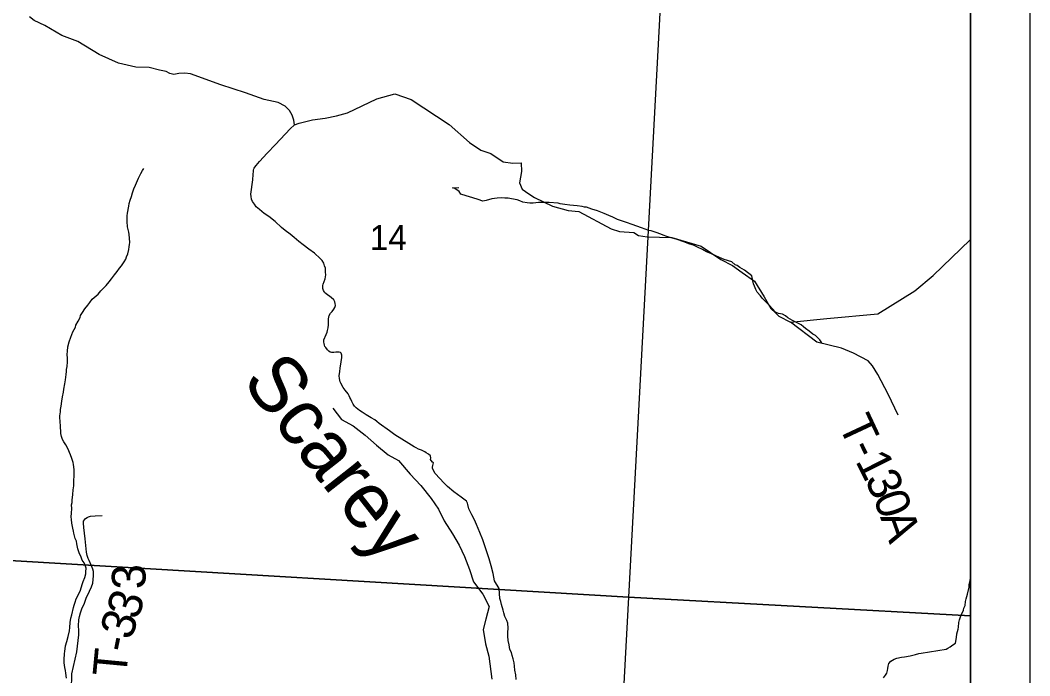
# Model space of a CAD drawing. Extents: x 0 to 45.4, y -2.2 to 22.
# Drawn here: x 7.301 to 9, y 17.906 to 19.01 of the extents above; entities that cross this region are included whole.
import ezdxf

# ---------------------------------------------------------------- set-up
doc = ezdxf.new("R2010")
doc.units = 0
for name, color, linetype in [('GM_X_Corporation', 7, 'Continuous'), ('GM_X_Minor_River', 7, 'Continuous'), ('GM_X_Minor_River_Text', 7, 'Continuous'), ('GM_X_Section_Text', 7, 'Continuous'), ('GM_X_Township_Road', 7, 'Continuous'), ('GM_X_Township_Road_Text', 7, 'Continuous'), ('SH_Data', 7, 'Continuous')]:
    doc.layers.add(name, color=color, linetype=linetype)

msp = doc.modelspace()

# ---------------------------------------------------------------- linework, layer by layer
at = {"layer": 'GM_X_Corporation'}
for points in [[(5.6021, 14.1), (7.0413, 14.1), (7.1146, 14.1136), (7.5608, 14.2194), (7.6244, 14.2444), (8.0832, 14.3972), (8.4711, 14.5406), (8.5907, 14.5823), (8.8228, 14.6772), (8.9, 14.7192), (8.9, 20.9), (2.1, 20.9)], [(5.6021, 14.1), (7.0413, 14.1), (7.1146, 14.1136), (7.5608, 14.2194), (7.6244, 14.2444), (8.0832, 14.3972), (8.4711, 14.5406), (8.5907, 14.5823), (8.8228, 14.6772), (8.9, 14.7192), (8.9, 20.9), (6.2942, 20.9), (6.2882, 20.8226), (6.2789, 20.7002), (6.2588, 20.2929), (6.2538, 20.2076), (6.2346, 20.0088), (6.2236, 19.8542), (6.181, 19.2539), (6.1763, 19.1885), (6.1061, 18.1607), (5.642, 18.1908)]]:
    msp.add_lwpolyline(points, dxfattribs=at)
for points in [[(8.3794, 19.064), (8.3245, 18.0384), (7.2262, 18.1039), (7.2905, 19.1287)], [(8.9, 18.0073), (8.9, 19.0371), (8.3794, 19.064), (8.3245, 18.0384)], [(7.2262, 18.1039), (8.3245, 18.0384), (8.2701, 17.0306), (7.1661, 17.098)], [(8.9, 16.9941), (8.9, 18.0073), (8.3245, 18.0384), (8.2701, 17.0306)]]:
    msp.add_lwpolyline(points, close=True, dxfattribs=at)
at = {"layer": 'GM_X_Minor_River'}
for points in [[(7.3803, 18.4407), (7.3801, 18.4468), (7.3805, 18.4529), (7.381, 18.4597), (7.3831, 18.4684), (7.3859, 18.4764), (7.3879, 18.4809), (7.3894, 18.4854), (7.3938, 18.4933), (7.3946, 18.4967), (7.3985, 18.5031), (7.4016, 18.5095), (7.4024, 18.5129), (7.4059, 18.5178), (7.4098, 18.5238), (7.4145, 18.5302), (7.4183, 18.5347), (7.4222, 18.5403), (7.4322, 18.5485), (7.4365, 18.5541), (7.4454, 18.5634), (7.4504, 18.5694), (7.4543, 18.5743), (7.4597, 18.581), (7.4643, 18.587), (7.4682, 18.5923), (7.4713, 18.5964), (7.4756, 18.6028), (7.4787, 18.6077), (7.4799, 18.6115), (7.4819, 18.6164), (7.4835, 18.6236), (7.484, 18.6281), (7.4848, 18.6319), (7.4853, 18.6357), (7.4846, 18.6429), (7.484, 18.649), (7.4837, 18.6528), (7.4816, 18.6619), (7.481, 18.6711), (7.4807, 18.676), (7.4808, 18.6806), (7.4812, 18.6851), (7.4837, 18.6965), (7.4842, 18.701), (7.4861, 18.7067), (7.4882, 18.7131), (7.4898, 18.7191), (7.4922, 18.7259), (7.4949, 18.7323), (7.4997, 18.7437), (7.504, 18.7516), (7.5067, 18.7568), (7.5087, 18.7602)], [(8.65, 18.4667), (8.6467, 18.4716), (8.643, 18.4751), (8.6393, 18.479), (8.6351, 18.4813), (8.6288, 18.4864), (8.6224, 18.4907), (8.6191, 18.4934), (8.615, 18.4969), (8.6007, 18.5043), (8.5928, 18.5086), (8.5887, 18.5121), (8.5838, 18.5149), (8.5804, 18.5153), (8.577, 18.5161), (8.5722, 18.5185), (8.5666, 18.5243), (8.5621, 18.5293), (8.5573, 18.5339), (8.5539, 18.5374), (8.5495, 18.542), (8.5465, 18.5459), (8.5413, 18.552), (8.5391, 18.5563), (8.5366, 18.562), (8.5351, 18.5658), (8.5337, 18.5708), (8.5319, 18.5792), (8.5196, 18.5889), (8.5121, 18.5935), (8.5076, 18.5967), (8.5042, 18.5982), (8.4983, 18.6029), (8.4858, 18.6069), (8.4727, 18.6124), (8.4629, 18.6168), (8.4561, 18.6199), (8.449, 18.6239), (8.4408, 18.6278), (8.434, 18.6309), (8.428, 18.6329), (8.4178, 18.6369), (8.405, 18.6409), (8.3926, 18.6446), (8.3892, 18.6458), (8.3828, 18.6481), (8.379, 18.6493), (8.3711, 18.6525), (8.3628, 18.6549), (8.3587, 18.6558), (8.3527, 18.6578), (8.3466, 18.6602), (8.3308, 18.6657), (8.3214, 18.6693), (8.3143, 18.6717), (8.306, 18.6745), (8.2985, 18.6781), (8.2913, 18.6812), (8.2834, 18.6844), (8.2725, 18.6888), (8.2631, 18.6919), (8.2537, 18.6948), (8.2503, 18.6952), (8.2469, 18.6964), (8.2382, 18.6973), (8.2257, 18.6983), (8.2174, 18.6996), (8.2095, 18.7008), (8.2061, 18.7017), (8.191, 18.703), (8.1732, 18.703), (8.1644, 18.702), (8.1587, 18.7017), (8.1542, 18.7022), (8.147, 18.7034), (8.1418, 18.7054), (8.1373, 18.7074), (8.1278, 18.7091), (8.1221, 18.7099), (8.1165, 18.7104), (8.1104, 18.7105), (8.1036, 18.7102), (8.0945, 18.7089), (8.0853, 18.7064), (8.0793, 18.7053), (8.0717, 18.7081), (8.0627, 18.7109), (8.0514, 18.7138), (8.0424, 18.717), (8.0394, 18.7216), (8.0323, 18.7263), (8.0285, 18.7278), (8.0391, 18.728)], [(7.3788, 17.9026), (7.3774, 17.911), (7.3771, 17.9152), (7.3757, 17.9205), (7.3751, 17.9281), (7.3748, 17.9331), (7.3754, 17.9441), (7.3758, 17.9475), (7.3771, 17.9566), (7.3791, 17.9641), (7.3815, 17.9724), (7.3836, 17.9819), (7.3845, 17.9876), (7.385, 17.9959), (7.3859, 18.0031), (7.3875, 18.0092), (7.3907, 18.0213), (7.3916, 18.0251), (7.3935, 18.03), (7.3952, 18.0356), (7.3995, 18.0443), (7.4022, 18.0507), (7.4054, 18.0602), (7.407, 18.0651), (7.4094, 18.0719), (7.4111, 18.0779), (7.4115, 18.0813), (7.4116, 18.0874), (7.4102, 18.0927), (7.4083, 18.0962), (7.4054, 18.1012), (7.4032, 18.1058), (7.3999, 18.1134), (7.3978, 18.1199), (7.396, 18.1283), (7.3957, 18.1329), (7.3935, 18.1375), (7.3911, 18.1466), (7.3907, 18.15), (7.3893, 18.1546), (7.3876, 18.163), (7.3869, 18.1695), (7.3866, 18.174), (7.3871, 18.1801), (7.3876, 18.1881), (7.3873, 18.1938), (7.3882, 18.1979), (7.3882, 18.2021), (7.3892, 18.2112), (7.3901, 18.2192), (7.3909, 18.226), (7.3911, 18.2351), (7.3916, 18.2431), (7.3917, 18.2465), (7.3914, 18.2533), (7.3904, 18.2621), (7.3901, 18.2655), (7.3876, 18.272), (7.3854, 18.2781), (7.3811, 18.2888), (7.3774, 18.295), (7.3741, 18.3003), (7.3722, 18.3042), (7.3704, 18.3088), (7.369, 18.3141), (7.3691, 18.3175), (7.3684, 18.3247), (7.3679, 18.3361), (7.3676, 18.3396), (7.3676, 18.3437), (7.3685, 18.3506), (7.3686, 18.3544), (7.3698, 18.36), (7.3711, 18.3684), (7.372, 18.3756), (7.3736, 18.3835), (7.3745, 18.3888), (7.3762, 18.3975), (7.3766, 18.4009), (7.377, 18.4047), (7.3775, 18.4089), (7.378, 18.4134), (7.3788, 18.4184), (7.3789, 18.4218), (7.3797, 18.4271), (7.3802, 18.4347), (7.3803, 18.4407)], [(7.8271, 18.3569), (7.8414, 18.3379), (7.861, 18.3272), (7.8814, 18.3112), (7.9003, 18.2944), (7.9199, 18.2784), (7.9373, 18.2685), (7.9569, 18.2456), (7.975, 18.2266), (7.9923, 18.2045), (8.0051, 18.187), (8.0141, 18.1672), (8.0284, 18.1452), (8.0397, 18.1261), (8.0487, 18.1071), (8.0569, 18.0851), (8.0637, 18.0645), (8.0795, 18.044), (8.09, 18.0227), (8.0846, 18.0014), (8.08, 17.984), (8.0837, 17.9604), (8.0896, 17.9392), (8.0948, 17.9004)], [(8.859, 17.9509), (8.8622, 17.9527), (8.866, 17.9549), (8.8706, 17.9586), (8.8752, 17.9615), (8.8769, 17.971), (8.8774, 17.9767), (8.8794, 17.9846), (8.8802, 17.988), (8.8807, 17.996), (8.8819, 18.0006), (8.884, 18.007), (8.8883, 18.0168), (8.8887, 18.0202), (8.8911, 18.0247), (8.892, 18.0315), (8.8928, 18.0361), (8.8952, 18.0436), (8.8981, 18.0557), (8.8981, 18.0599), (8.8993, 18.0641), (8.9, 18.0707)], [(8.7537, 17.9028), (8.7572, 17.9073), (8.7592, 17.9107), (8.7604, 17.9153), (8.7608, 17.9187), (8.7616, 17.9228), (8.7629, 17.927), (8.7659, 17.9307), (8.7717, 17.9341), (8.7763, 17.9359), (8.7843, 17.9376), (8.7892, 17.9383), (8.7987, 17.9397), (8.8078, 17.9422), (8.8131, 17.9436), (8.8169, 17.9447), (8.859, 17.9509)]]:
    msp.add_lwpolyline(points, dxfattribs=at)
at = {"layer": 'GM_X_Township_Road'}
for points in [[(7.7626, 18.8337), (7.7614, 18.8414), (7.7584, 18.8501), (7.7542, 18.8578), (7.7469, 18.8649), (7.7348, 18.8711), (7.7116, 18.8762), (7.6799, 18.8874), (7.6385, 18.9007), (7.5873, 18.9196), (7.5779, 18.9206), (7.5679, 18.9201), (7.5592, 18.9184), (7.5525, 18.9201), (7.5467, 18.9235), (7.5354, 18.9253), (7.5181, 18.9303), (7.4953, 18.9307), (7.4661, 18.9375), (7.4335, 18.9518), (7.3976, 18.974), (7.3711, 18.9841), (7.3424, 19.0007), (7.3246, 19.0091), (7.3164, 19.0153)], [(7.7626, 18.8337), (7.7704, 18.8362), (7.7925, 18.8417), (7.8139, 18.8446), (7.8332, 18.8486), (7.8516, 18.8537), (7.901, 18.8773), (7.9311, 18.8858), (7.9591, 18.8761), (8.0227, 18.8344), (8.057, 18.8039), (8.0759, 18.7911), (8.093, 18.7853), (8.1139, 18.7715), (8.13, 18.7689), (8.1437, 18.7694), (8.1445, 18.7549), (8.1412, 18.7358), (8.1455, 18.7253), (8.157, 18.7172), (8.1662, 18.7113), (8.1968, 18.6968), (8.2233, 18.6894), (8.2412, 18.6878), (8.2952, 18.6585), (8.3093, 18.6542), (8.3337, 18.6526), (8.3414, 18.6475), (8.3562, 18.645), (8.3975, 18.6439), (8.447, 18.6291), (8.4801, 18.6072), (8.4995, 18.597), (8.5158, 18.5848), (8.5367, 18.5705), (8.5531, 18.544), (8.5643, 18.5246), (8.5722, 18.5169), (8.5775, 18.5113), (8.5972, 18.5014), (8.6584, 18.5075), (8.7441, 18.5153), (8.8064, 18.5542), (8.8375, 18.5801), (8.8998, 18.6398), (8.9, 18.64)], [(8.1358, 17.8999), (8.1348, 17.9078), (8.1333, 17.916), (8.1327, 17.9224), (8.1319, 17.9283), (8.1307, 17.9347), (8.1289, 17.9405), (8.1276, 17.9454), (8.1251, 17.9506), (8.1237, 17.9583), (8.1223, 17.9659), (8.1217, 17.9733), (8.1215, 17.9792), (8.1218, 17.9867), (8.1215, 17.9949), (8.1196, 17.9995), (8.1165, 18.0063), (8.1147, 18.0124), (8.1139, 18.0169), (8.111, 18.0265), (8.1095, 18.0311), (8.1082, 18.0363), (8.1067, 18.0532), (8.0993, 18.0663), (8.0967, 18.0787), (8.0936, 18.0915), (8.0899, 18.1032), (8.0813, 18.1301), (8.0792, 18.1352), (8.0742, 18.1473), (8.0686, 18.1611), (8.0652, 18.1688), (8.0608, 18.177), (8.058, 18.1827), (8.0561, 18.1875), (8.0542, 18.1947), (8.0534, 18.197), (8.0517, 18.2001), (8.0495, 18.2021), (8.0432, 18.2068), (8.0305, 18.2162), (8.0198, 18.225), (8.0144, 18.2306), (7.9993, 18.2469), (7.9956, 18.2531), (7.9946, 18.2558), (7.9945, 18.2577), (7.9952, 18.26), (7.9964, 18.2646), (7.9949, 18.2656), (7.9926, 18.2685), (7.9916, 18.2702), (7.9917, 18.2728), (7.9912, 18.2768), (7.9878, 18.2792), (7.9839, 18.2817), (7.982, 18.2832), (7.9785, 18.2851), (7.976, 18.2862), (7.9714, 18.2879), (7.967, 18.2898), (7.9638, 18.2915), (7.9548, 18.2974), (7.9434, 18.3048), (7.9315, 18.312), (7.9221, 18.3186), (7.9052, 18.3308), (7.9009, 18.3341), (7.8976, 18.337), (7.8913, 18.3407), (7.8829, 18.3458), (7.8766, 18.3501), (7.8721, 18.353), (7.8664, 18.3574), (7.8634, 18.3603), (7.861, 18.3633), (7.8589, 18.3678), (7.8574, 18.372), (7.8558, 18.3749), (7.8547, 18.3775), (7.8527, 18.381), (7.8479, 18.3872), (7.8445, 18.3918), (7.8406, 18.3986), (7.8393, 18.4012), (7.8385, 18.4038), (7.8381, 18.4067), (7.8379, 18.411), (7.8385, 18.4182), (7.8392, 18.4241), (7.8412, 18.4347), (7.8421, 18.4422), (7.8421, 18.4457), (7.8414, 18.4478), (7.8408, 18.4492), (7.8398, 18.4505), (7.8379, 18.4511), (7.8354, 18.4511), (7.8322, 18.4508), (7.8288, 18.4502), (7.825, 18.4503), (7.8223, 18.4511), (7.8205, 18.4525), (7.8181, 18.4549), (7.818, 18.4551), (7.815, 18.4586), (7.8137, 18.4603), (7.813, 18.4626), (7.8123, 18.4653), (7.8118, 18.468), (7.8116, 18.4702), (7.8118, 18.472), (7.816, 18.4809), (7.8173, 18.4846), (7.8181, 18.4874), (7.819, 18.4919), (7.8195, 18.4972), (7.8197, 18.5011), (7.8198, 18.5071), (7.8201, 18.5098), (7.821, 18.5128), (7.8232, 18.5164), (7.8261, 18.5197), (7.8289, 18.5232), (7.8306, 18.5259), (7.8313, 18.5294), (7.8312, 18.5327), (7.8303, 18.5358), (7.8285, 18.5391), (7.8244, 18.543), (7.8158, 18.549), (7.8132, 18.5513), (7.8123, 18.5528), (7.8112, 18.5549), (7.8102, 18.5579), (7.81, 18.5605), (7.8099, 18.5607), (7.8103, 18.5633), (7.8109, 18.5655), (7.8123, 18.5701), (7.8141, 18.5744), (7.815, 18.581), (7.8149, 18.5858), (7.8144, 18.5922), (7.8132, 18.5964), (7.8118, 18.6005), (7.809, 18.6051), (7.8055, 18.6086), (7.796, 18.6177), (7.7865, 18.6245), (7.7769, 18.6315), (7.77, 18.6371), (7.762, 18.6441), (7.755, 18.6495), (7.7467, 18.6557), (7.7406, 18.6609), (7.73, 18.6708), (7.7191, 18.6795), (7.7116, 18.6846), (7.7033, 18.6911), (7.6979, 18.6957), (7.6949, 18.6999), (7.692, 18.7048), (7.6903, 18.7087), (7.6893, 18.7131), (7.6889, 18.7171), (7.6899, 18.7246), (7.6914, 18.7332), (7.6924, 18.7409), (7.6931, 18.7501), (7.6935, 18.7555), (7.6937, 18.7575), (7.6942, 18.7593), (7.6948, 18.7608), (7.6957, 18.7622), (7.6977, 18.7649), (7.7038, 18.7721), (7.7162, 18.7857), (7.7304, 18.8006), (7.7552, 18.827), (7.7626, 18.8337)], [(8.7782, 18.3451), (8.7617, 18.3802), (8.7441, 18.4134), (8.7354, 18.4281), (8.7278, 18.4366), (8.7035, 18.4493), (8.6831, 18.4575), (8.6418, 18.4679), (8.5972, 18.5014)], [(7.403, 18.0142), (7.4044, 18.0188), (7.4088, 18.0283), (7.4126, 18.0389), (7.4151, 18.0438), (7.4177, 18.0489), (7.4206, 18.0561), (7.4229, 18.062), (7.4239, 18.0683), (7.4243, 18.0743), (7.4243, 18.0779), (7.424, 18.0817), (7.4232, 18.0856), (7.4209, 18.0913), (7.4168, 18.1001), (7.4153, 18.1036), (7.4134, 18.1089), (7.4124, 18.1142), (7.4102, 18.137), (7.408, 18.1561), (7.4071, 18.1632), (7.4074, 18.1665), (7.409, 18.169), (7.4109, 18.1712), (7.4134, 18.1729), (7.4159, 18.1741), (7.4192, 18.1749), (7.4271, 18.1754), (7.4389, 18.1759)], [(7.3846, 17.8752), (7.3867, 17.8843), (7.3877, 17.9003), (7.3878, 17.9099), (7.3959, 17.9466), (7.3994, 17.9753), (7.3993, 17.9828), (7.3992, 17.9907), (7.3994, 18.0003), (7.4005, 18.0059), (7.4024, 18.0124), (7.403, 18.0142)]]:
    msp.add_lwpolyline(points, dxfattribs=at)
at = {"layer": 'SH_Data'}
for p, q in [((9, 21), (9, 14)), ((8.9, 20.9), (8.9, 14.1))]:
    msp.add_line(p, q, dxfattribs=at)

# ---------------------------------------------------------------- texts
at = {"layer": 'GM_X_Minor_River_Text'}
msp.add_text('Scarey', height=0.09468, rotation=308.1241, dxfattribs=at).set_placement((7.6722, 18.4016))
at = {"layer": 'GM_X_Section_Text'}
msp.add_text('14', height=0.04186, rotation=0, dxfattribs=at).set_placement((7.8892, 18.623))
at = {"layer": 'GM_X_Township_Road_Text'}
for s, rotation, p in [('T', 295.0707, (8.6768, 18.3293)), ('-', 295.5066, (8.695, 18.2904)), ('1', 296.7734, (8.7056, 18.2681)), ('3', 295.2817, (8.7212, 18.2372)), ('0', 289.9467, (8.7357, 18.2068)), ('A', 289.6227, (8.7476, 18.174)), ('3', 91.1693, (7.5123, 18.0524)), ('3', 72.2637, (7.4987, 17.9989)), ('3', 71.2116, (7.4871, 17.9647)), ('-', 78.4472, (7.4829, 17.9437)), ('T', 84.6136, (7.4791, 17.903))]:
    msp.add_text(s, height=0.0568, rotation=rotation, dxfattribs=at).set_placement(p)

doc.saveas('drawing.dxf')
